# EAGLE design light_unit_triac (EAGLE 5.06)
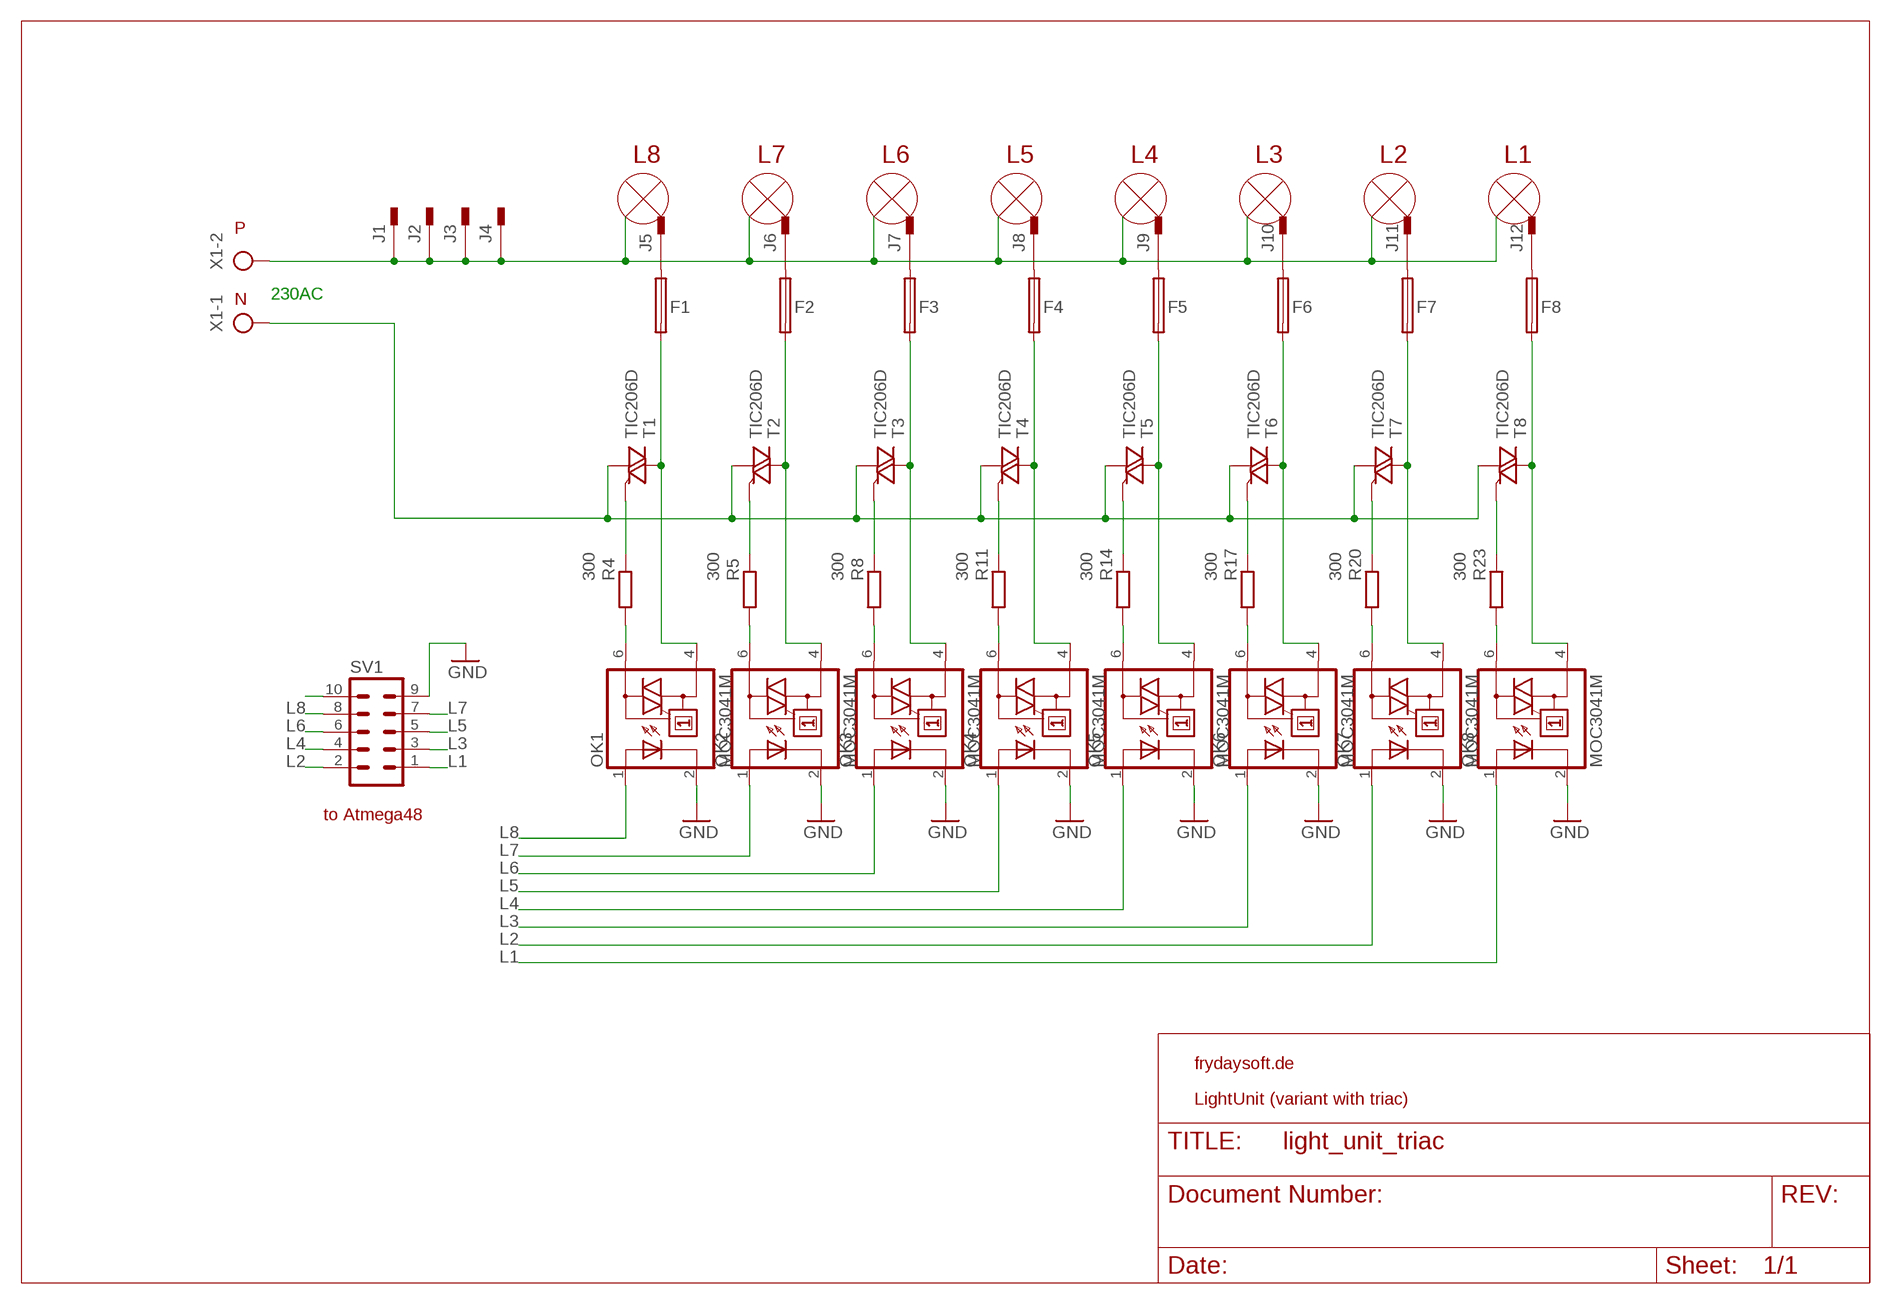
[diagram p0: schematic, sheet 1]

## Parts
F1  FUSESHK20L  [SHK20L]
F2  FUSESHK20L  [SHK20L]
F3  FUSESHK20L  [SHK20L]
F4  FUSESHK20L  [SHK20L]
F5  FUSESHK20L  [SHK20L]
F6  FUSESHK20L  [SHK20L]
F7  FUSESHK20L  [SHK20L]
F8  FUSESHK20L  [SHK20L]
J1  PIN262409-1  [62409-1]
J2  PIN262409-1  [62409-1]
J3  PIN262409-1  [62409-1]
J4  PIN262409-1  [62409-1]
J5  PIN262409-1  [62409-1]
J6  PIN262409-1  [62409-1]
J7  PIN262409-1  [62409-1]
J8  PIN262409-1  [62409-1]
J9  PIN262409-1  [62409-1]
J10  PIN262409-1  [62409-1]
J11  PIN262409-1  [62409-1]
J12  PIN262409-1  [62409-1]
OK1  MOC3041M  [DIL06]
OK2  MOC3041M  [DIL06]
OK3  MOC3041M  [DIL06]
OK4  MOC3041M  [DIL06]
OK5  MOC3041M  [DIL06]
OK6  MOC3041M  [DIL06]
OK7  MOC3041M  [DIL06]
OK8  MOC3041M  [DIL06]
R4  300  R-EU_0207/10  [0207/10]
R5  300  R-EU_0204/7  [0204/7]
R8  300  R-EU_0204/7  [0204/7]
R11  300  R-EU_0204/7  [0204/7]
R14  300  R-EU_0204/7  [0204/7]
R17  300  R-EU_0204/7  [0204/7]
R20  300  R-EU_0204/7  [0204/7]
R23  300  R-EU_0204/7  [0204/7]
SV1  ML10  [ML10]
T1  TIC206D  [TO220BV]
T2  TIC206D  [TO220BV]
T3  TIC206D  [TO220BV]
T4  TIC206D  [TO220BV]
T5  TIC206D  [TO220BV]
T6  TIC206D  [TO220BV]
T7  TIC206D  [TO220BV]
T8  TIC206D  [TO220BV]
X1  AK500/2  [AK500/2]

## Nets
GND: OK1.2(C) OK2.2(C) OK3.2(C) OK4.2(C) OK5.2(C) OK6.2(C) OK7.2(C) OK8.2(C) SV1.9
L1: OK8.1(A) SV1.1
L2: OK7.1(A) SV1.2
L3: OK6.1(A) SV1.3
L4: OK5.1(A) SV1.4
L5: OK4.1(A) SV1.5
L6: OK3.1(A) SV1.6
L7: OK2.1(A) SV1.7
L8: OK1.1(A) SV1.8
N$1: F1.1A J5.A1
N$2: R4.2 T1.G
N$3: OK1.6(A2) R4.1
N$4: F1.2A OK1.4(A1) T1.T2(A2)
N$5: OK2.6(A2) R5.1
N$6: OK3.6(A2) R8.1
N$7: F2.1A J6.A1
N$8: OK4.6(A2) R11.1
N$9: OK5.6(A2) R14.1
N$10: R5.2 T2.G
N$11: R8.2 T3.G
N$12: OK6.6(A2) R17.1
N$13: F3.1A J7.A1
N$14: OK7.6(A2) R20.1
N$15: OK8.6(A2) R23.1
N$16: R11.2 T4.G
N$17: R14.2 T5.G
N$19: F4.1A J8.A1
N$20: T1.T1(A1) T2.T1(A1) T3.T1(A1) T4.T1(A1) T5.T1(A1) T6.T1(A1) T7.T1(A1) T8.T1(A1) X1.1
N$21: R17.2 T6.G
N$22: R20.2 T7.G
N$23: R23.2 T8.G
N$24: F2.2A OK2.4(A1) T2.T2(A2)
N$25: F5.1A J9.A1
N$26: F3.2A OK3.4(A1) T3.T2(A2)
N$27: F4.2A OK4.4(A1) T4.T2(A2)
N$28: F5.2A OK5.4(A1) T5.T2(A2)
N$29: F6.2A OK6.4(A1) T6.T2(A2)
N$30: F7.2A OK7.4(A1) T7.T2(A2)
N$31: F6.1A J10.A1
N$32: F8.2A OK8.4(A1) T8.T2(A2)
N$36: J1.A1 J2.A1 J3.A1 J4.A1 X1.2
N$39: F7.1A J11.A1
N$49: F8.1A J12.A1
N$67: SV1.10
Unconnected: J1.A2(1.1) J2.A2(1.1) J3.A2(1.1) J4.A2(1.1) J5.A2(1.1) J6.A2(1.1) J7.A2(1.1) J8.A2(1.1) J9.A2(1.1) J10.A2(1.1) J11.A2(1.1) J12.A2(1.1)

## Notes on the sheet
- L8 | L7 | L6 | L5 | L4 | L3 | L2 | L1
- P
- 230AC
- N
- to Atmega48
- frydaysoft.de
- LightUnit (variant with triac)

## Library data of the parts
F1-F8 = fuse:FUSE: Fuse
J1-J12 = con-faston:PIN2: Flachstecker Typ Tyco/Electronics/AMP TAB, FASTON
OK1-OK8 = optocoupler:MOC30*: 6-Pin DIP Zero-Cross Optoisolators Triac Driver Output (250/400 Volt Peak) Source: http://www.fairchildsemi.com/ds/MO/MOC3043-M.pdf
R4 R5 R8 R11 R14 R17 R20 R23 = rcl:R-EU_: RESISTOR, European symbol
SV1 = con-ml:ML10: HARTING
T1-T8 = triac:TIC206: TRIAC Source: http://www.bourns.com/pdfs/tic206.pdf
X1 = con-ptr500:AK500/2: CONNECTOR

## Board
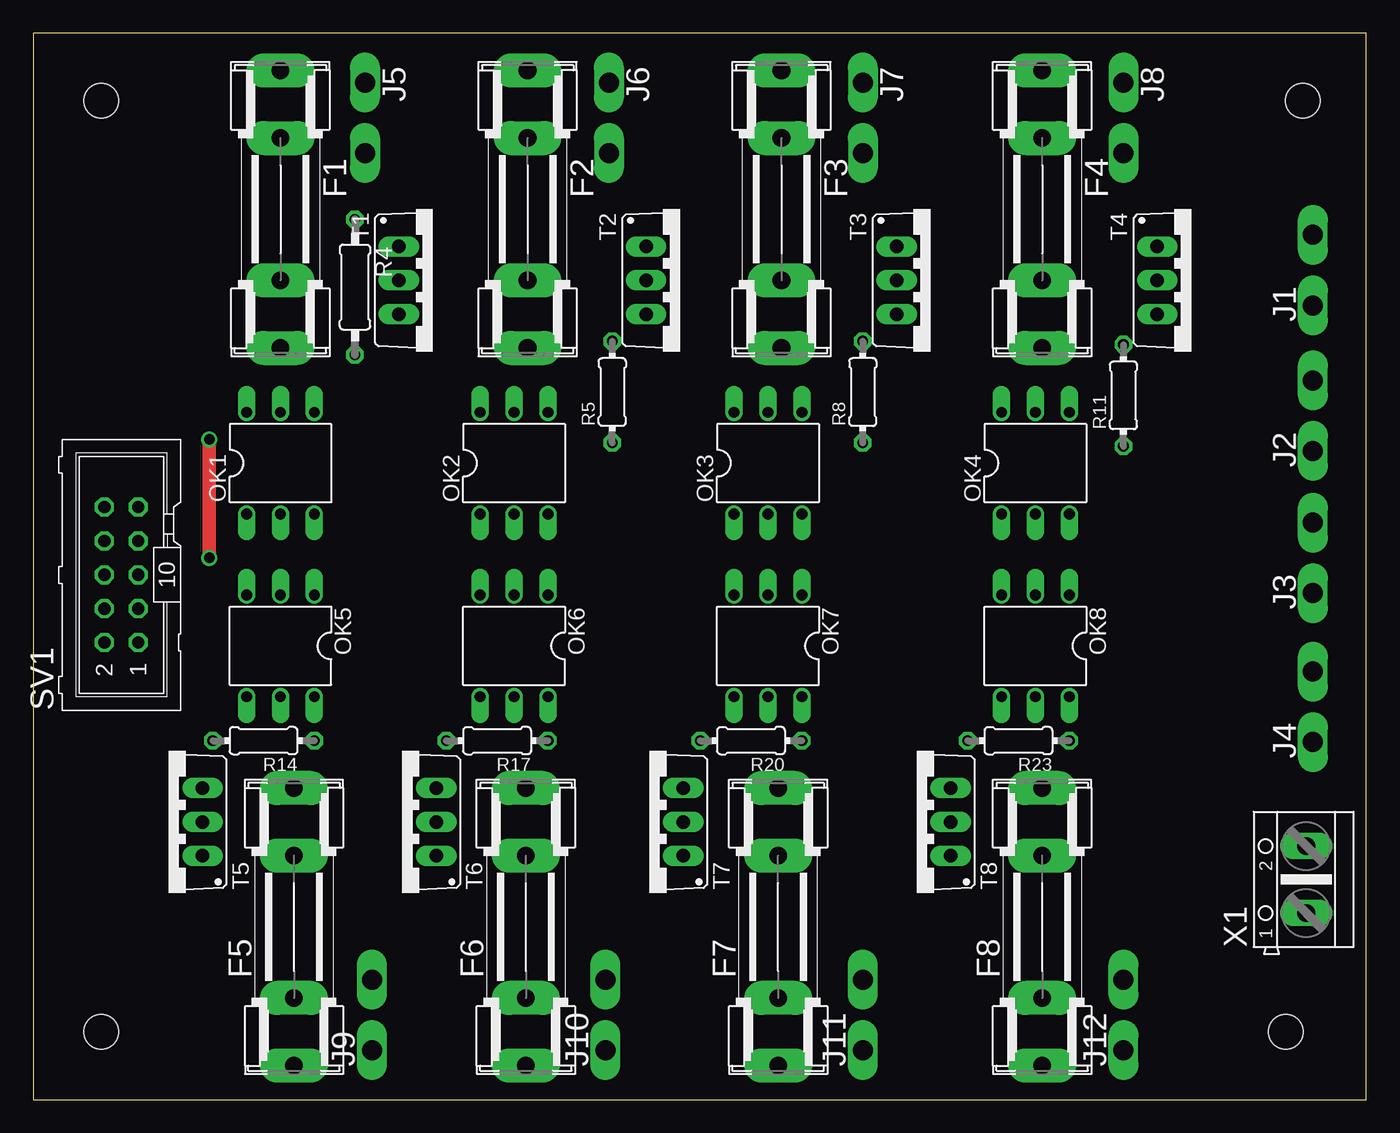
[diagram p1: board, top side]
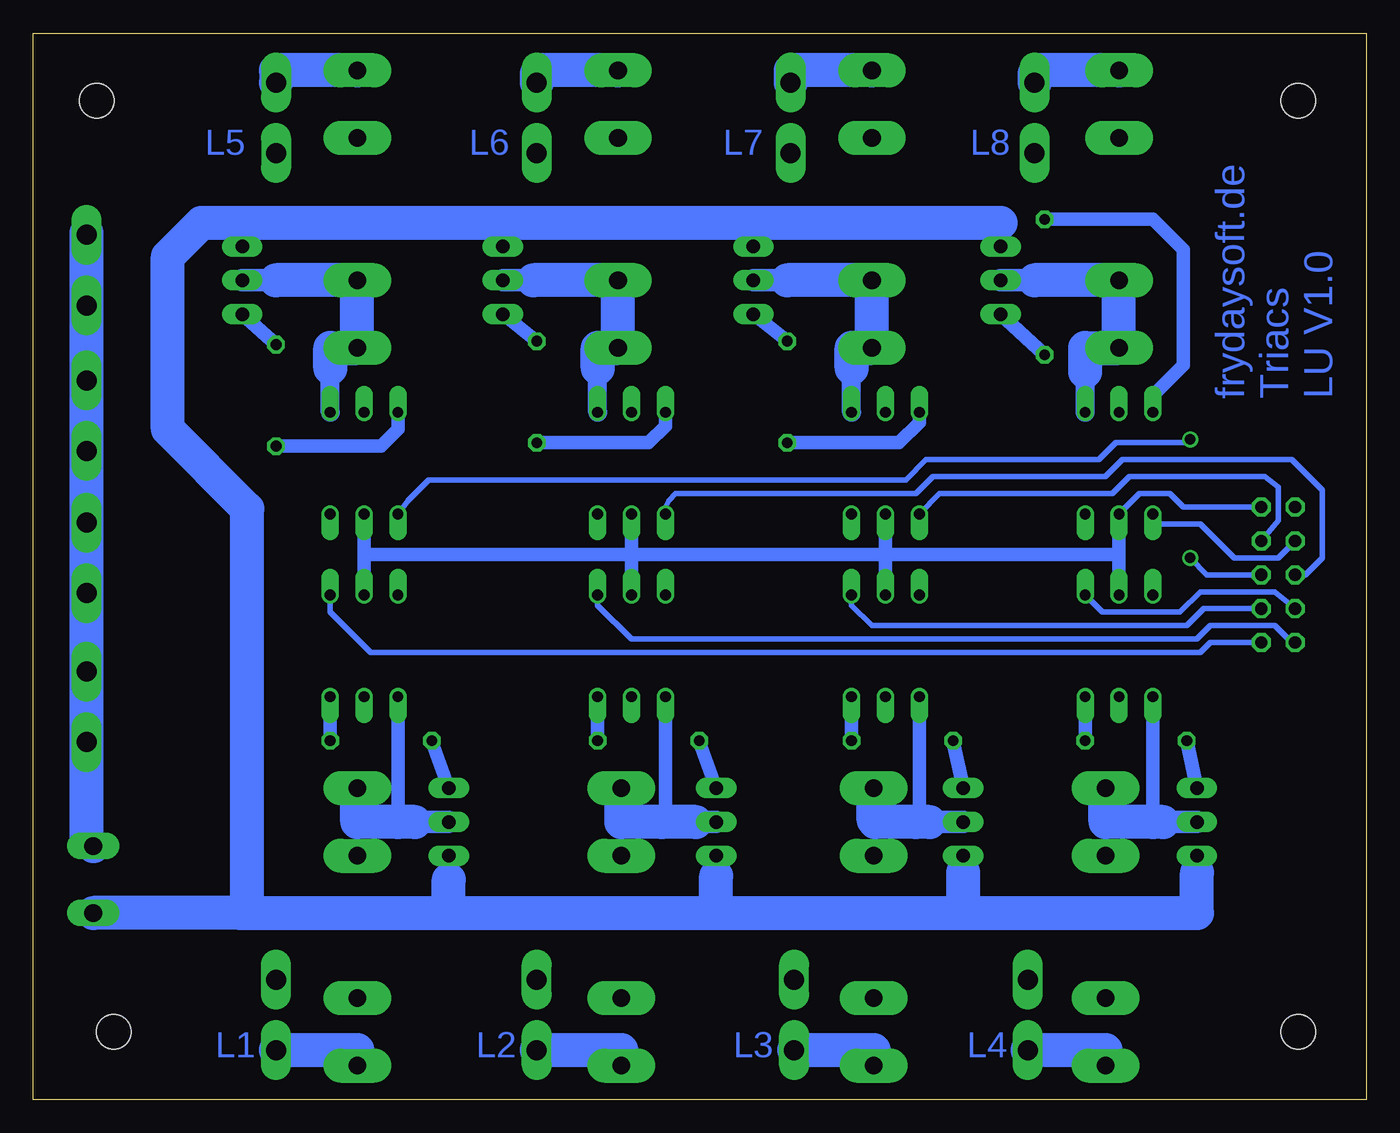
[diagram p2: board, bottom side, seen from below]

Size 100 x 80 mm. Coordinates in mm from the lower left corner, seen from the top.
Outline: 0,0 100,0 100,80 0,80 0,0
Copper layers (1*16): Top 0.035mm / dielectric 1.5mm / Bottom 0.035mm
Design rules "default": minimum track width 10mil, minimum drill 24mil, track to track 8mil, track to pad 8mil, pad to pad 8mil, via to via 8mil, smd to smd 8mil, copper to edge 40mil, drill to drill 8mil, minimum pad ring 10mil, minimum via ring 8mil, stop-mask expansion 4mil, vias tented up to drill 0mil, thermal gap 10mil
Holes 2.6 mm at 5.08,74.93 5.08,5.08 93.98,5.08 95.25,74.93

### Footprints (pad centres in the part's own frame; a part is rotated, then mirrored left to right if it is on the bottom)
SHK20L = drill 1.321 pad 2.54 long: 1A -10.414,0; 1B -5.334,0; 2A 10.414,0; 2B 5.334,0
62409-1 = drill 1.5 pad 1.9 long: A1 -2.65,0; A2 2.65,0
DIL06 = drill 0.813 offset: 1 -2.54,-3.81; 2 0,-3.81; 3 2.54,-3.81; 4 2.54,3.81; 5 0,3.81; 6 -2.54,3.81
0207/10 = drill 0.813 octagon: 1 -5.08,0; 2 5.08,0
0204/7 = drill 0.813 octagon: 1 -3.81,0; 2 3.81,0
ML10 = drill 0.914 octagon: 1 -5.08,-1.27; 2 -5.08,1.27; 3 -2.54,-1.27; 4 -2.54,1.27; 5 0,-1.27; 6 0,1.27; 7 2.54,-1.27; 8 2.54,1.27; 9 5.08,-1.27; 10 5.08,1.27
TO220BV = drill 1.016 long: G 2.54,-2.54; T1 -2.54,-2.54; T2 0,-2.54
AK500/2 = drill 1.321 long: 1 -2.515,0; 2 2.515,0

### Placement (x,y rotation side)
F1  18.54,66.8 270 top
F2  37.08,66.8 270 top
F3  56.13,66.8 270 top
F4  75.69,66.8 270 top
F5  19.56,12.95 90 top
F6  36.96,12.95 90 top
F7  55.88,12.95 90 top
F8  75.69,12.95 90 top
J1  96.01,62.23 90 top
J2  96.01,51.31 90 top
J3  96.01,40.64 90 top
J4  96.01,29.46 90 top
J5  24.89,73.66 270 top
J6  43.18,73.66 270 top
J7  62.23,73.66 270 top
J8  81.79,73.66 270 top
J9  25.4,6.35 90 top
J10  42.93,6.35 90 top
J11  62.23,6.35 90 top
J12  81.79,6.35 90 top
OK1  18.54,47.75 0 top
OK2  36.07,47.75 0 top
OK3  55.12,47.75 0 top
OK4  75.18,47.75 0 top
OK5  18.54,34.04 180 top
OK6  36.07,34.04 180 top
OK7  55.12,34.04 180 top
OK8  75.18,34.04 180 top
R4  24.13,60.96 270 top
R5  43.43,53.09 90 top
R8  62.23,53.09 90 top
R11  81.79,52.83 90 top
R14  17.27,26.92 180 top
R17  34.8,26.92 180 top
R20  53.85,26.92 180 top
R23  73.91,26.92 180 top
SV1  6.6,39.37 90 top
T1  29.97,61.47 270 top
T2  48.51,61.47 270 top
T3  67.31,61.47 270 top
T4  86.87,61.47 270 top
T5  10.16,20.83 90 top
T6  27.69,20.83 90 top
T7  46.23,20.83 90 top
T8  66.29,20.83 90 top
X1  95.5,16.51 90 top

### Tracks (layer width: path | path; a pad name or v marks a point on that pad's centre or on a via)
GND
  Bottom 0.406: SV1.9 13.72,44.45 14.73,45.47 17.02,45.47 OK1.2
  Bottom 1.016: 18.54,40.89 OK5.2 | OK1.2 18.54,40.89 | 36.07,40.89 OK6.2 | 18.54,40.89 36.07,40.89 | 55.12,40.89 OK7.2 | 36.07,40.89 OK2.2 | 36.07,40.89 55.12,40.89 | 75.18,40.89 OK8.2 | 75.18,40.89 OK4.2 | 55.12,40.89 OK3.2 | 55.12,40.89 75.18,40.89
L1
  Bottom 0.406: SV1.1 11.68,34.29 12.45,33.53 74.68,33.53 77.72,36.58 OK8.1
L2
  Bottom 0.406: SV1.2 5.59,34.29 6.86,35.56 11.68,35.56 12.7,34.54 55.12,34.54 57.66,37.08 OK7.1
L3
  Bottom 0.406: SV1.3 12.19,36.83 13.46,35.56 37.08,35.56 38.61,37.08 OK6.1
L4
  Bottom 0.406: SV1.4 6.86,38.1 12.45,38.1 13.97,36.58 19.81,36.58 OK5.1
L5  (via drill 0.8)
  Top 1.016: v13.21,40.64 v13.21,49.53
  Bottom 0.406: SV1.5 11.94,39.37 v13.21,40.64 | v13.21,49.53 13.46,49.28 18.8,49.28 20.07,48.01 33.02,48.01 34.54,46.48 70.36,46.48 71.88,44.96 OK4.1
L6
  Bottom 0.406: SV1.6 4.57,39.37 3.3,40.64 3.3,45.72 5.59,48.01 18.29,48.01 19.56,46.74 32.51,46.74 33.78,45.47 51.82,45.47 52.32,44.96 52.58,44.45 OK3.1
L7
  Bottom 0.406: SV1.7 6.6,43.43 6.6,45.97 7.62,46.74 17.78,46.74 19.05,45.47 32,45.47 OK2.1
L8
  Bottom 0.406: SV1.8 6.6,40.64 9.91,40.64 12.45,43.18 16,43.18 OK1.1
N$1
  Bottom 2.54: F1.1A 24.64,77.22 24.89,76.96 J5.A1
N$2
  Bottom 1.016: R4.2 T1.G
N$3
  Bottom 1.016: OK1.6 16,52.83 13.72,55.12 13.72,63.75 16,66.04 R4.1
N$4
  Bottom 1.422: OK1.4 21.08,54.61
  Bottom 1.676: 24.89,61.47 T1.T2
  Bottom 2.54: 21.08,54.61 21.08,56.39 F1.2A 18.54,61.47 24.89,61.47
N$5
  Bottom 1.016: OK2.6 33.53,50.8 35.05,49.28 R5.1
N$6
  Bottom 1.016: OK3.6 52.58,50.55 53.85,49.28 R8.1
N$7
  Bottom 2.54: F2.1A 43.18,77.22 J6.A1
N$8
  Bottom 1.016: OK4.6 72.64,50.29 73.91,49.02 R11.1
N$9
  Bottom 1.016: R14.1 OK5.6
N$10
  Bottom 1.016: R5.2 T2.G
N$11
  Bottom 1.016: R8.2 T3.G
N$12
  Bottom 1.016: R17.1 OK6.6
N$13
  Bottom 2.54: F3.1A 61.98,77.22 62.23,76.96 J7.A1
N$14
  Bottom 1.016: R20.1 OK7.6
N$15
  Bottom 1.016: R23.1 OK8.6
N$16
  Bottom 1.016: R11.2 T4.G
N$17
  Bottom 1.016: T5.G R14.2
N$19
  Bottom 2.54: F4.1A 81.79,77.22 J8.A1
N$20
  Bottom 1.016: 12.7,17.02 T5.T1 | 30.23,17.02 T6.T1 | 48.77,16.76 T7.T1 | 68.83,16.51 T8.T1
  Bottom 1.422: T1.T1 27.43,65.79 45.47,65.79 45.97,65.02 T2.T1 45.97,65.79 | 64.77,65.79 T3.T1 | 87.38,65.79 84.58,65.28 84.33,65.53 T4.T1
  Bottom 2.54: 30.23,13.97 12.7,13.97 12.7,17.02 | 30.23,13.97 48.77,13.97 | 48.77,13.97 68.83,13.97 | 83.95,13.97 84.45,13.97 | X1.1 84.45,13.99 83.95,13.97 | 68.83,13.97 83.95,13.97 | 68.83,13.97 68.83,16.51 | 83.95,13.97 83.95,44.32 89.92,50.29 89.92,63.25 87.38,65.79 64.77,65.79 45.97,65.79 27.43,65.79 | 30.23,13.97 30.23,17.02 | 48.77,13.97 48.77,16.76
N$21
  Bottom 1.016: T6.G R17.2
N$22
  Bottom 1.016: T7.G R20.2
N$23
  Bottom 1.016: T8.G R23.2
N$24
  Bottom 1.422: OK2.4 38.61,54.86
  Bottom 1.676: 43.43,61.47 T2.T2
  Bottom 2.54: 38.61,54.86 38.61,56.39 F2.2A 37.08,61.47 43.43,61.47
N$25
  Bottom 2.54: F5.1A 19.56,3.7 J9.A1
N$26
  Bottom 1.422: OK3.4 57.66,54.86
  Bottom 1.676: 62.48,61.47 T3.T2
  Bottom 2.54: 57.66,54.86 57.66,56.39 F3.2A 56.13,61.47 62.48,61.47
N$27
  Bottom 1.422: OK4.4 77.72,54.86
  Bottom 1.676: 81.79,61.47 T4.T2
  Bottom 2.54: 77.72,54.86 77.72,56.39 F4.2A 75.69,61.47 81.79,61.47
N$28
  Bottom 1.016: 16,20.83 OK5.4
  Bottom 1.676: T5.T2 15.24,20.83
  Bottom 2.54: 15.24,20.83 16,20.83 19.56,20.83 F5.2A
N$29
  Bottom 1.016: OK6.4 33.53,21.08 33.78,20.83
  Bottom 1.676: T6.T2 32.77,20.83
  Bottom 2.54: F6.2A 36.96,20.95 36.83,20.83 33.78,20.83 32.77,20.83
N$30
  Bottom 1.016: OK7.4 52.58,21.08 52.83,20.83
  Bottom 1.676: T7.T2 50.29,20.83
  Bottom 2.54: 50.29,20.83 52.83,20.83 55.88,20.83 F7.2A
N$31
  Bottom 2.54: F6.1A 36.96,3.7 J10.A1
N$32
  Bottom 1.016: 72.64,20.83 OK8.4
  Bottom 1.676: T8.T2 71.37,20.83
  Bottom 2.54: F8.2A 75.69,20.83 72.64,20.83 71.37,20.83
N$36
  Bottom 2.54: X1.2 96.01,19.53 J4.A1 J3.A1 J2.A1 J1.A1 96.01,65.02
N$39
  Bottom 2.54: F7.1A 55.88,3.7 J11.A1
N$49
  Bottom 2.54: F8.1A 75.69,3.7 J12.A1

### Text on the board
Bottom: L8 | L7 | L6 | L5 | LU V1.0 | Triacs | frydaysoft.de | L4 | L3 | L2 | L1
